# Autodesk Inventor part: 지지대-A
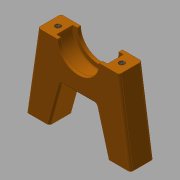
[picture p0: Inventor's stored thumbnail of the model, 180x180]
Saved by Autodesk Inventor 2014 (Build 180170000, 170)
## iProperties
Created: 2018-01
Part Number: 지지대-A
Material: 일반
Document SubType Name: Modeling
Designer: mduedu
Density: 1 g/cm^3
Appearance: 주황색
Mass: 8.09801 g
Surface Area: 38.5771 cm^2
Volume: 8.09801 cm^3
Author: mduedu
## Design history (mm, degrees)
sketch "스케치1"
  geometry: L1 (-22.5, 0)-(22.5, 0); L2 (22.5, 0)-(17.5, 34); L3 (17.5, 34)-(-17.5, 34); L4 (-17.5, 34)-(-22.5, 0); 3 further points
  constraints: 8 end point, 2 midpoint, 1 coincident, 1 horizontal, 1 parallel, 1 vertical alignment
  dimensions: "d0" = 45 distance of L1.start L1.end; "d3" = 35 distance of L2.end L3.end; "d4" = 34 vertical distance of L1.end L2.end
extrude "돌출1" new body sketch "스케치1" stored distance "d5" = 10; taper "d6" = 0 deg
sketch "스케치2"
  geometry: L1 (-12.5, 0)-(12.5, 0); L2 (12.5, 0)-(7.5, 18); L3 (7.5, 18)-(-7.5, 18); L4 (-7.5, 18)-(-12.5, 0); L5 (-22.5, 0)-(22.5, 0) reference; 4 further points
  constraints: 8 end point, 4 midpoint, 1 horizontal, 1 parallel, 1 vertical alignment
  dimensions: "d7" = 10 distance of L1.start L5.start; "d8" = 10 distance of L1.end L5.end (derived); "d9" = 15 distance of L2.end L3.end; "d10" = 18 distance between parallel lines of L1 L3
extrude "돌출2" cut sketch "스케치2" stored distance "d11" = 10; taper "d12" = 0 deg
sketch "스케치3"
  geometry: L1 (-17.5, 34)-(17.5, 34) reference; C1 r 11 at (0, 34); C2 r 9 at (0, 34); 1 further point
  constraints: 2 centre point, 1 coincident, 1 midpoint
  dimensions: "d13" = 22 diameter of C1; "d16" = 18 diameter of C2
extrude "돌출3" cut sketch "스케치3" stored distance "d14" = 7; taper "d15" = 0 deg
extrude "돌출4" cut sketch "스케치3" stored distance "d17" = 7; taper "d18" = 0 deg
fillet "모깎기1" dims "d19" = 0.3
fillet "모깎기2" dims "d20" = 1
fillet "모깎기3" dims "d21" = 1
fillet "모깎기4" dims "d22" = 1
sketch "스케치4"
  geometry: 2 further points
  constraints: 2 other
hole "구멍1" sketch "스케치4" at (-22.771, -3.5), (4.771, -3.5) diameter "d23" = 2.459; stored, may be unused: countersink angle "d27" = 90 deg, drill point angle "d29" = 120 deg; dims "d24" = 4.5, "d25" = 4, "d26" = 2, "d28" = 6
sketch "스케치5"
  geometry: 4 further points
  constraints: 4 other
hole "구멍2" sketch "스케치5" at (40, 4), (5, -27), (40, -27), (5, 4) diameter "d30" = 2.459; stored, may be unused: countersink angle "d34" = 90 deg, drill point angle "d36" = 120 deg; dims "d31" = 6.9, "d32" = 4, "d33" = 2, "d35" = 8.4
node "솔리드1"
